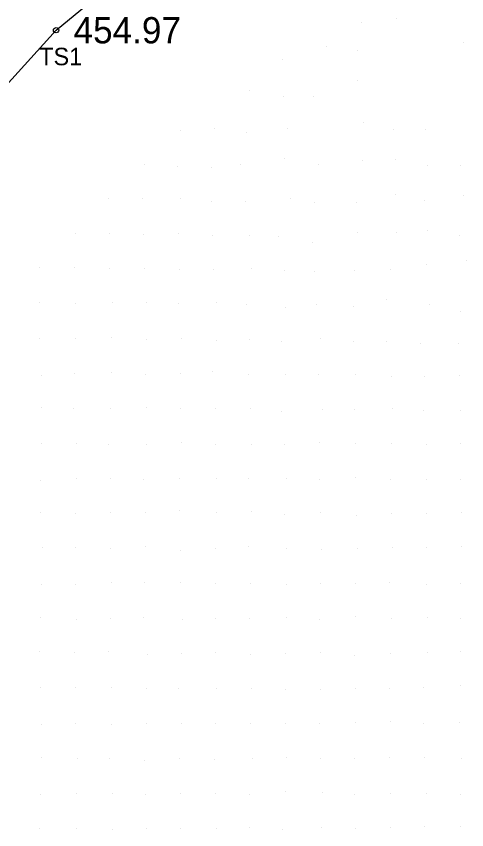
# Model space of a CAD drawing. Extents: x 1747760 to 1751131, y 649333 to 653784.
# Drawn here: x 1749099.9 to 1749125.63, y 651450.72 to 651497.17 of the extents above; entities that cross this region are included whole.
import ezdxf

# ---------------------------------------------------------------- set-up
doc = ezdxf.new("R2010")
doc.units = 0
for name, color, linetype in [('RD_DTM_BkLn2', 7, 'Continuous'), ('RD_DTM_BkLn_txCode', 7, 'Continuous'), ('RD_DTM_Spot', 7, 'Continuous'), ('RD_EX_TX_Misc_ELEV', 7, 'Continuous'), ('RD_SMD_Locator', 7, 'Continuous')]:
    doc.layers.add(name, color=color, linetype=linetype)

msp = doc.modelspace()

# ---------------------------------------------------------------- linework, layer by layer
at = {"layer": 'RD_DTM_BkLn2'}
msp.add_lwpolyline([(1749072.449, 651463.568), (1749102.17, 651496.369), (1749126.542, 651516.467), (1749148.35, 651529.918), (1749165.728, 651545.441)], dxfattribs=at)
at = {"layer": 'RD_DTM_Spot'}
for p, q in [((1749119.592, 651496.826), (1749119.592, 651496.826)), ((1749121.633, 651497.034), (1749121.633, 651497.034)), ((1749117.622, 651495.458), (1749117.622, 651495.458)), ((1749125.444, 651495.678), (1749125.444, 651495.678)), ((1749119.407, 651495.235), (1749119.407, 651495.235)), ((1749115.083, 651494.68), (1749115.083, 651494.68)), ((1749119.372, 651493.471), (1749119.372, 651493.471)), ((1749113.217, 651492.956), (1749113.217, 651492.956)), ((1749115.172, 651492.57), (1749115.172, 651492.57)), ((1749116.883, 651492.602), (1749116.883, 651492.602)), ((1749119.759, 651491.11), (1749119.759, 651491.11)), ((1749109.295, 651490.644), (1749109.295, 651490.644)), ((1749111.246, 651490.748), (1749111.246, 651490.748)), ((1749115.371, 651490.756), (1749115.371, 651490.756)), ((1749121.434, 651490.679), (1749121.434, 651490.679)), ((1749123.251, 651490.704), (1749123.251, 651490.704)), ((1749113.063, 651490.548), (1749113.063, 651490.548)), ((1749115.202, 651489.041), (1749115.202, 651489.041)), ((1749119.658, 651488.938), (1749119.658, 651488.938)), ((1749121.584, 651488.983), (1749121.584, 651488.983)), ((1749107.24, 651488.68), (1749107.24, 651488.68)), ((1749109.123, 651488.613), (1749109.123, 651488.613)), ((1749111.031, 651488.534), (1749111.031, 651488.534)), ((1749112.696, 651488.679), (1749112.696, 651488.679)), ((1749117.17, 651488.684), (1749117.17, 651488.684)), ((1749123.383, 651488.654), (1749123.383, 651488.654)), ((1749125.26, 651488.651), (1749125.26, 651488.651)), ((1749121.545, 651487.018), (1749121.545, 651487.018)), ((1749125.464, 651486.934), (1749125.464, 651486.934)), ((1749105.191, 651486.734), (1749105.191, 651486.734)), ((1749107.122, 651486.774), (1749107.122, 651486.774)), ((1749109.26, 651486.787), (1749109.26, 651486.787)), ((1749111.071, 651486.618), (1749111.071, 651486.618)), ((1749113.008, 651486.565), (1749113.008, 651486.565)), ((1749115.565, 651486.752), (1749115.565, 651486.752)), ((1749116.958, 651486.515), (1749116.958, 651486.515)), ((1749119.336, 651486.526), (1749119.336, 651486.526)), ((1749123.219, 651486.646), (1749123.219, 651486.646)), ((1749103.309, 651484.739), (1749103.309, 651484.739)), ((1749105.246, 651484.774), (1749105.246, 651484.774)), ((1749107.145, 651484.73), (1749107.145, 651484.73)), ((1749109.148, 651484.739), (1749109.148, 651484.739)), ((1749111.129, 651484.644), (1749111.129, 651484.644)), ((1749113.231, 651484.621), (1749113.231, 651484.621)), ((1749119.416, 651484.809), (1749119.416, 651484.809)), ((1749121.612, 651484.824), (1749121.612, 651484.824)), ((1749123.365, 651484.934), (1749123.365, 651484.934)), ((1749125.228, 651484.666), (1749125.228, 651484.666)), ((1749114.851, 651484.599), (1749114.851, 651484.599)), ((1749116.828, 651484.275), (1749116.828, 651484.275)), ((1749101.237, 651482.85), (1749101.237, 651482.85)), ((1749103.248, 651482.844), (1749103.248, 651482.844)), ((1749107.245, 651482.75), (1749107.245, 651482.75)), ((1749113.343, 651482.76), (1749113.343, 651482.76)), ((1749123.33, 651482.99), (1749123.33, 651482.99)), ((1749125.61, 651483.205), (1749125.61, 651483.205)), ((1749105.233, 651482.744), (1749105.233, 651482.744)), ((1749109.225, 651482.723), (1749109.225, 651482.723)), ((1749111.144, 651482.68), (1749111.144, 651482.68)), ((1749115.22, 651482.64), (1749115.22, 651482.64)), ((1749116.913, 651482.573), (1749116.913, 651482.573)), ((1749119.24, 651482.651), (1749119.24, 651482.651)), ((1749121.293, 651482.702), (1749121.293, 651482.702)), ((1749121.062, 651480.984), (1749121.062, 651480.984)), ((1749101.245, 651480.815), (1749101.245, 651480.815)), ((1749103.263, 651480.746), (1749103.263, 651480.746)), ((1749105.37, 651480.843), (1749105.37, 651480.843)), ((1749107.327, 651480.839), (1749107.327, 651480.839)), ((1749109.179, 651480.745), (1749109.179, 651480.745)), ((1749111.328, 651480.796), (1749111.328, 651480.796)), ((1749113.057, 651480.686), (1749113.057, 651480.686)), ((1749115.255, 651480.529), (1749115.255, 651480.529)), ((1749117.054, 651480.689), (1749117.054, 651480.689)), ((1749119.181, 651480.602), (1749119.181, 651480.602)), ((1749123.518, 651480.683), (1749123.518, 651480.683)), ((1749125.3, 651480.314), (1749125.3, 651480.314)), ((1749101.202, 651478.783), (1749101.202, 651478.783)), ((1749103.294, 651478.765), (1749103.294, 651478.765)), ((1749105.344, 651478.796), (1749105.344, 651478.796)), ((1749107.318, 651478.698), (1749107.318, 651478.698)), ((1749109.315, 651478.743), (1749109.315, 651478.743)), ((1749111.324, 651478.628), (1749111.324, 651478.628)), ((1749113.239, 651478.692), (1749113.239, 651478.692)), ((1749115.055, 651478.573), (1749115.055, 651478.573)), ((1749117.271, 651478.744), (1749117.271, 651478.744)), ((1749119.149, 651478.584), (1749119.149, 651478.584)), ((1749121.036, 651478.583), (1749121.036, 651478.583)), ((1749122.973, 651478.499), (1749122.973, 651478.499)), ((1749125.137, 651478.456), (1749125.137, 651478.456)), ((1749103.239, 651476.751), (1749103.239, 651476.751)), ((1749105.341, 651476.805), (1749105.341, 651476.805)), ((1749107.273, 651476.715), (1749107.273, 651476.715)), ((1749109.259, 651476.78), (1749109.259, 651476.78)), ((1749111.134, 651476.886), (1749111.134, 651476.886)), ((1749113.154, 651476.722), (1749113.154, 651476.722)), ((1749117.179, 651476.735), (1749117.179, 651476.735)), ((1749101.342, 651476.682), (1749101.342, 651476.682)), ((1749115.249, 651476.697), (1749115.249, 651476.697)), ((1749119.298, 651476.701), (1749119.298, 651476.701)), ((1749121.311, 651476.617), (1749121.311, 651476.617)), ((1749123.24, 651476.586), (1749123.24, 651476.586)), ((1749125.241, 651476.655), (1749125.241, 651476.655)), ((1749101.352, 651474.815), (1749101.352, 651474.815)), ((1749103.189, 651474.747), (1749103.189, 651474.747)), ((1749105.279, 651474.752), (1749105.279, 651474.752)), ((1749107.338, 651474.823), (1749107.338, 651474.823)), ((1749109.263, 651474.772), (1749109.263, 651474.772)), ((1749111.281, 651474.768), (1749111.281, 651474.768)), ((1749113.29, 651474.777), (1749113.29, 651474.777)), ((1749115.074, 651474.623), (1749115.074, 651474.623)), ((1749117.415, 651474.697), (1749117.415, 651474.697)), ((1749119.239, 651474.718), (1749119.239, 651474.718)), ((1749121.363, 651474.751), (1749121.363, 651474.751)), ((1749123.175, 651474.643), (1749123.175, 651474.643)), ((1749125.257, 651474.662), (1749125.257, 651474.662)), ((1749101.321, 651472.776), (1749101.321, 651472.776)), ((1749103.34, 651472.793), (1749103.34, 651472.793)), ((1749105.182, 651472.705), (1749105.182, 651472.705)), ((1749107.341, 651472.726), (1749107.341, 651472.726)), ((1749109.33, 651472.83), (1749109.33, 651472.83)), ((1749111.296, 651472.696), (1749111.296, 651472.696)), ((1749113.332, 651472.718), (1749113.332, 651472.718)), ((1749115.217, 651472.727), (1749115.217, 651472.727)), ((1749117.21, 651472.823), (1749117.21, 651472.823)), ((1749119.3, 651472.779), (1749119.3, 651472.779)), ((1749121.311, 651472.746), (1749121.311, 651472.746)), ((1749123.345, 651472.716), (1749123.345, 651472.716)), ((1749125.292, 651472.767), (1749125.292, 651472.767)), ((1749101.308, 651470.68), (1749101.308, 651470.68)), ((1749103.346, 651470.76), (1749103.346, 651470.76)), ((1749105.303, 651470.801), (1749105.303, 651470.801)), ((1749107.16, 651470.744), (1749107.16, 651470.744)), ((1749109.248, 651470.776), (1749109.248, 651470.776)), ((1749111.334, 651470.79), (1749111.334, 651470.79)), ((1749113.187, 651470.771), (1749113.187, 651470.771)), ((1749115.332, 651470.799), (1749115.332, 651470.799)), ((1749117.222, 651470.715), (1749117.222, 651470.715)), ((1749119.301, 651470.814), (1749119.301, 651470.814)), ((1749121.267, 651470.728), (1749121.267, 651470.728)), ((1749123.329, 651470.738), (1749123.329, 651470.738)), ((1749125.263, 651470.727), (1749125.263, 651470.727)), ((1749101.304, 651468.826), (1749101.304, 651468.826)), ((1749105.299, 651468.835), (1749105.299, 651468.835)), ((1749107.297, 651468.819), (1749107.297, 651468.819)), ((1749109.247, 651468.929), (1749109.247, 651468.929)), ((1749111.331, 651468.858), (1749111.331, 651468.858)), ((1749113.342, 651468.868), (1749113.342, 651468.868)), ((1749125.303, 651468.826), (1749125.303, 651468.826)), ((1749103.264, 651468.77), (1749103.264, 651468.77)), ((1749115.241, 651468.73), (1749115.241, 651468.73)), ((1749117.303, 651468.805), (1749117.303, 651468.805)), ((1749119.334, 651468.681), (1749119.334, 651468.681)), ((1749121.308, 651468.794), (1749121.308, 651468.794)), ((1749123.334, 651468.777), (1749123.334, 651468.777)), ((1749101.373, 651466.817), (1749101.373, 651466.817)), ((1749103.261, 651466.845), (1749103.261, 651466.845)), ((1749105.292, 651466.776), (1749105.292, 651466.776)), ((1749107.285, 651466.896), (1749107.285, 651466.896)), ((1749109.305, 651466.682), (1749109.305, 651466.682)), ((1749111.301, 651466.787), (1749111.301, 651466.787)), ((1749113.15, 651466.881), (1749113.15, 651466.881)), ((1749115.348, 651466.78), (1749115.348, 651466.78)), ((1749117.305, 651466.722), (1749117.305, 651466.722)), ((1749119.41, 651466.78), (1749119.41, 651466.78)), ((1749121.389, 651466.846), (1749121.389, 651466.846)), ((1749123.308, 651466.811), (1749123.308, 651466.811)), ((1749125.345, 651466.868), (1749125.345, 651466.868)), ((1749101.367, 651464.717), (1749101.367, 651464.717)), ((1749103.292, 651464.735), (1749103.292, 651464.735)), ((1749105.316, 651464.811), (1749105.316, 651464.811)), ((1749107.228, 651464.824), (1749107.228, 651464.824)), ((1749109.27, 651464.844), (1749109.27, 651464.844)), ((1749111.3, 651464.775), (1749111.3, 651464.775)), ((1749113.284, 651464.796), (1749113.284, 651464.796)), ((1749115.325, 651464.718), (1749115.325, 651464.718)), ((1749117.252, 651464.793), (1749117.252, 651464.793)), ((1749119.298, 651464.773), (1749119.298, 651464.773)), ((1749121.207, 651464.834), (1749121.207, 651464.834)), ((1749123.35, 651464.72), (1749123.35, 651464.72)), ((1749125.284, 651464.755), (1749125.284, 651464.755)), ((1749101.261, 651462.859), (1749101.261, 651462.859)), ((1749105.278, 651462.787), (1749105.278, 651462.787)), ((1749107.174, 651462.856), (1749107.174, 651462.856)), ((1749111.287, 651462.8), (1749111.287, 651462.8)), ((1749113.24, 651462.804), (1749113.24, 651462.804)), ((1749115.338, 651462.829), (1749115.338, 651462.829)), ((1749119.26, 651462.903), (1749119.26, 651462.903)), ((1749121.304, 651462.793), (1749121.304, 651462.793)), ((1749123.4, 651462.828), (1749123.4, 651462.828)), ((1749103.321, 651462.748), (1749103.321, 651462.748)), ((1749109.383, 651462.737), (1749109.383, 651462.737)), ((1749117.23, 651462.74), (1749117.23, 651462.74)), ((1749125.256, 651462.751), (1749125.256, 651462.751)), ((1749101.239, 651460.891), (1749101.239, 651460.891)), ((1749103.241, 651460.86), (1749103.241, 651460.86)), ((1749105.193, 651460.871), (1749105.193, 651460.871)), ((1749107.368, 651460.719), (1749107.368, 651460.719)), ((1749109.31, 651460.809), (1749109.31, 651460.809)), ((1749111.293, 651460.825), (1749111.293, 651460.825)), ((1749113.288, 651460.74), (1749113.288, 651460.74)), ((1749115.279, 651460.769), (1749115.279, 651460.769)), ((1749117.26, 651460.826), (1749117.26, 651460.826)), ((1749119.224, 651460.694), (1749119.224, 651460.694)), ((1749121.247, 651460.775), (1749121.247, 651460.775)), ((1749123.396, 651460.848), (1749123.396, 651460.848)), ((1749125.282, 651460.876), (1749125.282, 651460.876)), ((1749101.275, 651458.82), (1749101.275, 651458.82)), ((1749103.259, 651458.825), (1749103.259, 651458.825)), ((1749105.328, 651458.839), (1749105.328, 651458.839)), ((1749107.311, 651458.809), (1749107.311, 651458.809)), ((1749109.189, 651458.803), (1749109.189, 651458.803)), ((1749111.352, 651458.778), (1749111.352, 651458.778)), ((1749113.342, 651458.788), (1749113.342, 651458.788)), ((1749115.305, 651458.75), (1749115.305, 651458.75)), ((1749117.299, 651458.733), (1749117.299, 651458.733)), ((1749119.277, 651458.809), (1749119.277, 651458.809)), ((1749121.2, 651458.799), (1749121.2, 651458.799)), ((1749123.178, 651458.865), (1749123.178, 651458.865)), ((1749125.295, 651458.937), (1749125.295, 651458.937)), ((1749103.276, 651456.787), (1749103.276, 651456.787)), ((1749105.324, 651456.735), (1749105.324, 651456.735)), ((1749107.341, 651456.78), (1749107.341, 651456.78)), ((1749109.312, 651456.78), (1749109.312, 651456.78)), ((1749111.268, 651456.77), (1749111.268, 651456.77)), ((1749113.282, 651456.789), (1749113.282, 651456.789)), ((1749115.256, 651456.798), (1749115.256, 651456.798)), ((1749117.228, 651456.76), (1749117.228, 651456.76)), ((1749119.3, 651456.822), (1749119.3, 651456.822)), ((1749121.252, 651456.916), (1749121.252, 651456.916)), ((1749123.161, 651456.807), (1749123.161, 651456.807)), ((1749125.238, 651456.855), (1749125.238, 651456.855)), ((1749101.324, 651456.717), (1749101.324, 651456.717)), ((1749101.314, 651454.814), (1749101.314, 651454.814)), ((1749103.404, 651454.805), (1749103.404, 651454.805)), ((1749105.236, 651454.774), (1749105.236, 651454.774)), ((1749107.24, 651454.677), (1749107.24, 651454.677)), ((1749109.234, 651454.811), (1749109.234, 651454.811)), ((1749111.213, 651454.712), (1749111.213, 651454.712)), ((1749113.377, 651454.767), (1749113.377, 651454.767)), ((1749115.352, 651454.826), (1749115.352, 651454.826)), ((1749117.253, 651454.782), (1749117.253, 651454.782)), ((1749119.239, 651454.809), (1749119.239, 651454.809)), ((1749121.208, 651454.831), (1749121.208, 651454.831)), ((1749123.225, 651454.852), (1749123.225, 651454.852)), ((1749125.341, 651454.799), (1749125.341, 651454.799)), ((1749101.278, 651452.754), (1749101.278, 651452.754)), ((1749103.364, 651452.78), (1749103.364, 651452.78)), ((1749105.37, 651452.779), (1749105.37, 651452.779)), ((1749107.26, 651452.732), (1749107.26, 651452.732)), ((1749109.252, 651452.759), (1749109.252, 651452.759)), ((1749111.286, 651452.79), (1749111.286, 651452.79)), ((1749113.236, 651452.725), (1749113.236, 651452.725)), ((1749115.272, 651452.879), (1749115.272, 651452.879)), ((1749117.366, 651452.825), (1749117.366, 651452.825)), ((1749119.233, 651452.743), (1749119.233, 651452.743)), ((1749121.289, 651452.77), (1749121.289, 651452.77)), ((1749123.339, 651452.794), (1749123.339, 651452.794)), ((1749125.249, 651452.717), (1749125.249, 651452.717)), ((1749101.246, 651450.805), (1749101.246, 651450.805)), ((1749103.313, 651450.772), (1749103.313, 651450.772)), ((1749105.384, 651450.718), (1749105.384, 651450.718)), ((1749107.331, 651450.762), (1749107.331, 651450.762)), ((1749109.267, 651450.808), (1749109.267, 651450.808)), ((1749111.319, 651450.794), (1749111.319, 651450.794)), ((1749113.239, 651450.864), (1749113.239, 651450.864)), ((1749115.108, 651450.752), (1749115.108, 651450.752)), ((1749117.354, 651450.851), (1749117.354, 651450.851)), ((1749119.27, 651450.778), (1749119.27, 651450.778)), ((1749121.25, 651450.819), (1749121.25, 651450.819)), ((1749123.226, 651450.905), (1749123.226, 651450.905)), ((1749125.245, 651450.896), (1749125.245, 651450.896))]:
    msp.add_line(p, q, dxfattribs=at)
at = {"layer": 'RD_SMD_Locator'}
msp.add_circle((1749102.17, 651496.369), 0.15, dxfattribs=at)

# ---------------------------------------------------------------- texts
at = {"layer": 'RD_DTM_BkLn_txCode'}
msp.add_text('TS1', height=1, dxfattribs=at).set_placement((1749101.21, 651494.369))
at = {"layer": 'RD_EX_TX_Misc_ELEV'}
msp.add_text('454.97', height=1.5, dxfattribs=at).set_placement((1749103.17, 651495.619))

doc.saveas('drawing.dxf')
